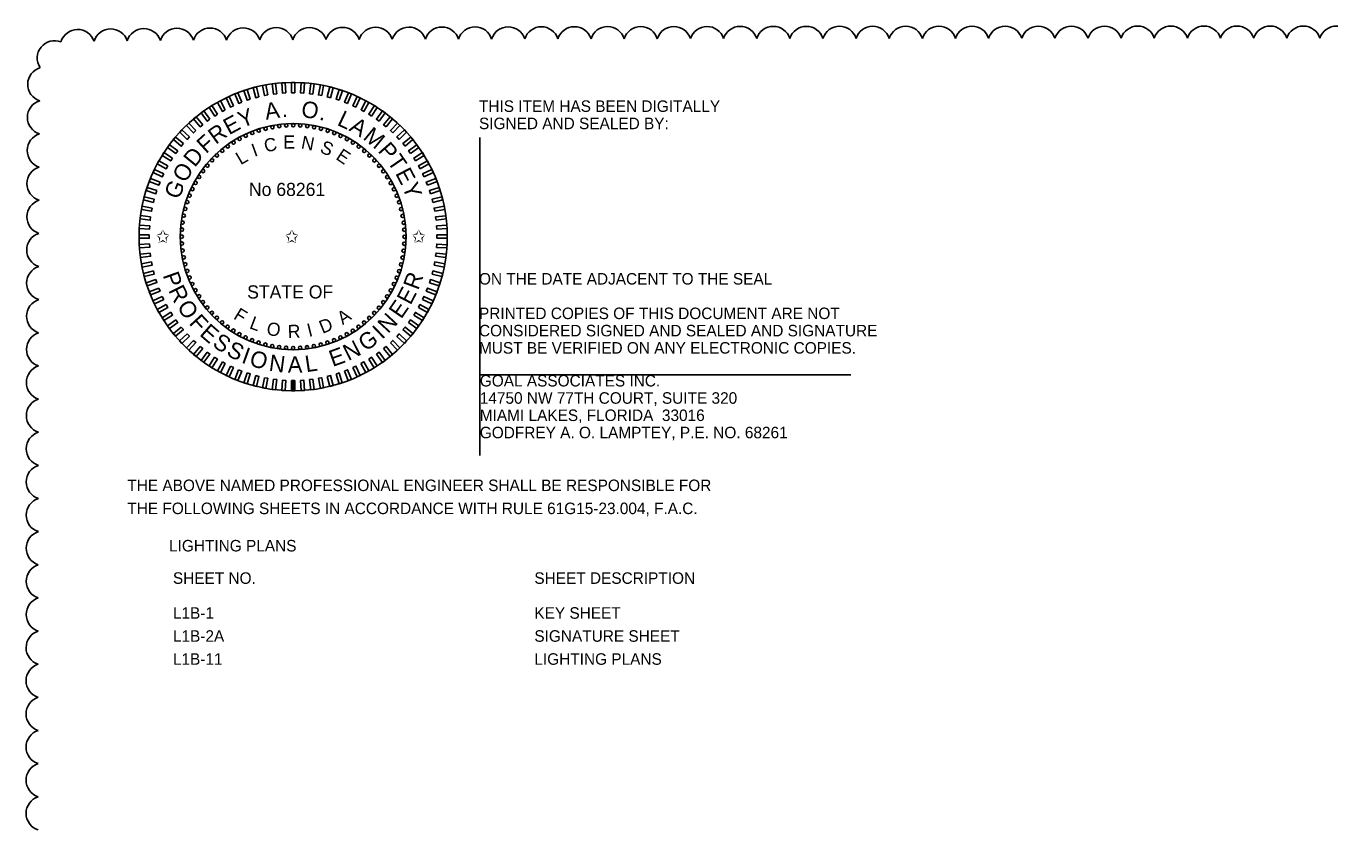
# Model space of a CAD drawing. Extents: x -811.2 to -755.6, y -2295.2 to -2235.1.
# Drawn here: x -811.11 to -803.18, y -2252.32 to -2247.44 of the extents above; entities that cross this region are included whole.
import ezdxf

# ---------------------------------------------------------------- set-up
doc = ezdxf.new("R2010")
doc.units = 0
for name, color, linetype in [('Cloud_dp', 7, 'Continuous'), ('Logo_dp', 7, 'Continuous'), ('NonPlottingEle_dp', 7, 'Continuous'), ('ScratchEle_dp', 7, 'Continuous'), ('TextMisc', 7, 'Continuous'), ('TextNotes', 7, 'Continuous')]:
    doc.layers.add(name, color=color, linetype=linetype)

msp = doc.modelspace()

# ---------------------------------------------------------------- linework, layer by layer
at = {"layer": 'Cloud_dp'}
for centre, start, end in [((-810.8012, -2247.5613), 18.59454, 163.59454), ((-810.5999, -2247.5581), 18.21421, 163.21421), ((-810.3985, -2247.5559), 18.04696, 163.04696), ((-810.197, -2247.5542), 17.94666, 162.94666), ((-809.9955, -2247.5527), 17.87787, 162.87787), ((-809.794, -2247.5515), 17.82689, 162.82689), ((-809.5924, -2247.5504), 17.78716, 162.78716), ((-809.3909, -2247.5495), 17.75505, 162.75505), ((-809.1894, -2247.5486), 17.72841, 162.72841), ((-808.9878, -2247.5478), 17.70584, 162.70584), ((-808.7863, -2247.5471), 17.6864, 162.6864), ((-808.5848, -2247.5465), 17.66942, 162.66942), ((-808.3832, -2247.546), 17.65443, 162.65443), ((-808.1817, -2247.5454), 17.64106, 162.64106), ((-807.9801, -2247.545), 17.62905, 162.62905), ((-807.7786, -2247.5445), 17.61817, 162.61817), ((-807.577, -2247.5441), 17.60826, 162.60826), ((-807.3755, -2247.5438), 17.59919, 162.59919), ((-807.174, -2247.5434), 17.59084, 162.59084), ((-806.9724, -2247.5431), 17.58312, 162.58312), ((-806.7709, -2247.5428), 17.57595, 162.57595), ((-806.5693, -2247.5426), 17.56928, 162.56928), ((-806.3678, -2247.5424), 17.56305, 162.56305), ((-806.1662, -2247.5421), 17.55721, 162.55721), ((-805.9647, -2247.5419), 17.55172, 162.55172), ((-805.7631, -2247.5418), 17.54655, 162.54655), ((-805.5616, -2247.5416), 17.54167, 162.54167), ((-805.3601, -2247.5415), 17.53705, 162.53705), ((-805.1585, -2247.5414), 17.53267, 162.53267), ((-804.957, -2247.5413), 17.52851, 162.52851), ((-804.7554, -2247.5412), 17.52455, 162.52455), ((-804.5539, -2247.5411), 17.52079, 162.52079), ((-804.3523, -2247.541), 17.51719, 162.51719), ((-804.1508, -2247.541), 17.51375, 162.51375), ((-803.9492, -2247.5409), 17.51046, 162.51046), ((-803.7477, -2247.5409), 17.50731, 162.50731), ((-803.5461, -2247.5409), 17.50428, 162.50428), ((-803.3446, -2247.5409), 17.50138, 162.50138), ((-803.143, -2247.5409), 17.5, 162.5), ((-810.9414, -2247.6297), 68.43954, 213.43954), ((-810.999, -2247.7891), 106.80445, 251.80445), ((-811.001, -2247.9905), 107.04367, 252.04367), ((-811.0025, -2248.192), 107.15618, 252.15618), ((-811.0035, -2248.3935), 107.22533, 252.22533), ((-811.0044, -2248.595), 107.27338, 252.27338), ((-811.0052, -2248.7966), 107.30928, 252.30928), ((-811.0058, -2248.9981), 107.33743, 252.33743), ((-811.0063, -2249.1996), 107.36027, 252.36027), ((-811.0068, -2249.4012), 107.37928, 252.37928), ((-811.0072, -2249.6027), 107.39543, 252.39543), ((-811.0075, -2249.8042), 107.40937, 252.40937), ((-811.0078, -2250.0058), 107.42156, 252.42156), ((-811.0081, -2250.2073), 107.43234, 252.43234), ((-811.0083, -2250.4089), 107.44197, 252.44197), ((-811.0085, -2250.6104), 107.45063, 252.45063), ((-811.0086, -2250.812), 107.45847, 252.45847), ((-811.0088, -2251.0135), 107.46563, 252.46563), ((-811.0089, -2251.2151), 107.47218, 252.47218), ((-811.009, -2251.4166), 107.47822, 252.47822), ((-811.009, -2251.6181), 107.4838, 252.4838), ((-811.0091, -2251.8197), 107.48899, 252.48899), ((-811.0091, -2252.0212), 107.49382, 252.49382), ((-811.0091, -2252.2228), 107.49843, 252.49843)]:
    msp.add_arc(centre, 0.1057, start, end, dxfattribs=at)
at = {"layer": 'Logo_dp'}
for p, q in [((-809.5001, -2249.6532), (-809.5003, -2249.5907)), ((-809.4901, -2249.6531), (-809.4903, -2249.5906)), ((-809.4801, -2249.6531), (-809.4803, -2249.5906))]:
    msp.add_line(p, q, dxfattribs=at)
for points in [[(-809.5897, -2247.8462), (-809.6097, -2247.8488), (-809.6175, -2247.7868), (-809.5975, -2247.7843)], [(-809.5349, -2247.8417), (-809.555, -2247.843), (-809.559, -2247.7806), (-809.5388, -2247.7794)], [(-809.4799, -2247.8406), (-809.5001, -2247.8406), (-809.5001, -2247.7782), (-809.4799, -2247.7782)], [(-809.425, -2247.843), (-809.4452, -2247.8417), (-809.4412, -2247.7794), (-809.4211, -2247.7807)], [(-809.3703, -2247.8488), (-809.3904, -2247.8463), (-809.3825, -2247.7843), (-809.3625, -2247.7868)], [(-809.8535, -2247.9195), (-809.8717, -2247.9281), (-809.8983, -2247.8716), (-809.8801, -2247.863)], [(-809.8028, -2247.8983), (-809.8215, -2247.9057), (-809.8445, -2247.8477), (-809.8258, -2247.8402)], [(-809.7508, -2247.8803), (-809.77, -2247.8865), (-809.7893, -2247.8271), (-809.7701, -2247.8209)], [(-809.6979, -2247.8656), (-809.7174, -2247.8706), (-809.7329, -2247.8101), (-809.7134, -2247.8051)], [(-809.6441, -2247.8542), (-809.6639, -2247.858), (-809.6756, -2247.7966), (-809.6558, -2247.7929)], [(-809.3162, -2247.858), (-809.336, -2247.8542), (-809.3243, -2247.7929), (-809.3045, -2247.7967)], [(-809.2626, -2247.8706), (-809.2822, -2247.8656), (-809.2667, -2247.8051), (-809.2471, -2247.8102)], [(-809.21, -2247.8866), (-809.2292, -2247.8803), (-809.2099, -2247.821), (-809.1907, -2247.8272)], [(-809.1585, -2247.9058), (-809.1773, -2247.8984), (-809.1543, -2247.8403), (-809.1355, -2247.8477)], [(-809.1083, -2247.9282), (-809.1266, -2247.9196), (-809.1, -2247.8631), (-809.0817, -2247.8717)], [(-809.9504, -2247.9714), (-809.9674, -2247.9822), (-810.0009, -2247.9295), (-809.9838, -2247.9186)], [(-809.9027, -2247.9439), (-809.9204, -2247.9537), (-809.9505, -2247.8989), (-809.9328, -2247.8892)], [(-809.0596, -2247.9537), (-809.0773, -2247.944), (-809.0473, -2247.8893), (-809.0296, -2247.899)], [(-809.0127, -2247.9823), (-809.0297, -2247.9715), (-808.9962, -2247.9187), (-808.9792, -2247.9296)], [(-810.0817, -2248.0708), (-810.0964, -2248.0846), (-810.1392, -2248.0391), (-810.1244, -2248.0253)], [(-810.04, -2248.0349), (-810.0556, -2248.0478), (-810.0954, -2247.9997), (-810.0798, -2247.9868)], [(-809.9962, -2248.0017), (-810.0125, -2248.0136), (-810.0492, -2247.9631), (-810.0329, -2247.9512)], [(-808.9676, -2248.0137), (-808.9839, -2248.0018), (-808.9472, -2247.9513), (-808.9308, -2247.9632)], [(-808.9245, -2248.0479), (-808.9401, -2248.035), (-808.9003, -2247.9869), (-808.8847, -2247.9998)], [(-808.8837, -2248.0847), (-808.8984, -2248.0709), (-808.8557, -2248.0254), (-808.841, -2248.0392)], [(-810.121, -2248.1092), (-810.1348, -2248.1239), (-810.1804, -2248.0812), (-810.1665, -2248.0665)], [(-808.8453, -2248.1241), (-808.8591, -2248.1093), (-808.8136, -2248.0666), (-808.7998, -2248.0813)], [(-810.192, -2248.1931), (-810.2039, -2248.2094), (-810.2544, -2248.1727), (-810.2426, -2248.1564)], [(-810.1579, -2248.15), (-810.1707, -2248.1656), (-810.2188, -2248.1258), (-810.206, -2248.1102)], [(-808.8094, -2248.1657), (-808.8223, -2248.1502), (-808.7742, -2248.1104), (-808.7613, -2248.1259)], [(-808.7762, -2248.2095), (-808.7881, -2248.1932), (-808.7376, -2248.1565), (-808.7257, -2248.1728)], [(-810.252, -2248.2852), (-810.2617, -2248.3028), (-810.3164, -2248.2728), (-810.3067, -2248.2551)], [(-810.2235, -2248.2382), (-810.2343, -2248.2552), (-810.287, -2248.2218), (-810.2762, -2248.2047)], [(-808.7459, -2248.2554), (-808.7567, -2248.2383), (-808.7039, -2248.2049), (-808.6931, -2248.2219)], [(-808.7184, -2248.303), (-808.7281, -2248.2853), (-808.6734, -2248.2552), (-808.6637, -2248.2729)], [(-810.2775, -2248.3338), (-810.2861, -2248.3521), (-810.3426, -2248.3255), (-810.334, -2248.3073)], [(-808.694, -2248.3523), (-808.7026, -2248.334), (-808.6461, -2248.3074), (-808.6375, -2248.3257)], [(-810.3192, -2248.4355), (-810.3254, -2248.4547), (-810.3848, -2248.4355), (-810.3786, -2248.4163)], [(-810.3, -2248.384), (-810.3074, -2248.4028), (-810.3654, -2248.3798), (-810.358, -2248.3611)], [(-808.6728, -2248.403), (-808.6802, -2248.3842), (-808.6222, -2248.3612), (-808.6147, -2248.38)], [(-808.6548, -2248.4549), (-808.661, -2248.4357), (-808.6016, -2248.4164), (-808.5954, -2248.4356)], [(-810.3351, -2248.4882), (-810.3401, -2248.5077), (-810.4006, -2248.4922), (-810.3956, -2248.4726)], [(-808.64, -2248.5079), (-808.6451, -2248.4883), (-808.5846, -2248.4728), (-808.5796, -2248.4924)], [(-810.3477, -2248.5417), (-810.3515, -2248.5615), (-810.4129, -2248.5498), (-810.4091, -2248.53)], [(-808.6287, -2248.5617), (-808.6325, -2248.5418), (-808.5711, -2248.5301), (-808.5673, -2248.55)], [(-810.3628, -2248.6505), (-810.3641, -2248.6707), (-810.4264, -2248.6668), (-810.4251, -2248.6466)], [(-810.357, -2248.5959), (-810.3595, -2248.6159), (-810.4215, -2248.6081), (-810.4189, -2248.588)], [(-808.6207, -2248.6161), (-808.6232, -2248.596), (-808.5613, -2248.5882), (-808.5588, -2248.6082)], [(-808.6162, -2248.6709), (-808.6174, -2248.6507), (-808.5551, -2248.6468), (-808.5539, -2248.6669)], [(-810.3652, -2248.7054), (-810.3652, -2248.7256), (-810.4276, -2248.7256), (-810.4276, -2248.7054)], [(-808.6151, -2248.7258), (-808.6151, -2248.7056), (-808.5527, -2248.7056), (-808.5527, -2248.7258)], [(-810.3641, -2248.7604), (-810.3628, -2248.7806), (-810.4251, -2248.7845), (-810.4264, -2248.7643)], [(-810.3595, -2248.8152), (-810.357, -2248.8352), (-810.4189, -2248.8431), (-810.4215, -2248.823)], [(-808.6233, -2248.8354), (-808.6207, -2248.8154), (-808.5588, -2248.8232), (-808.5613, -2248.8432)], [(-808.6175, -2248.7807), (-808.6162, -2248.7606), (-808.5539, -2248.7645), (-808.5551, -2248.7847)], [(-810.3516, -2248.8696), (-810.3478, -2248.8894), (-810.4091, -2248.9011), (-810.4129, -2248.8813)], [(-808.6325, -2248.8896), (-808.6287, -2248.8698), (-808.5674, -2248.8815), (-808.5712, -2248.9013)], [(-810.3402, -2248.9234), (-810.3352, -2248.9429), (-810.3957, -2248.9585), (-810.4007, -2248.9389)], [(-810.3255, -2248.9763), (-810.3192, -2248.9955), (-810.3786, -2249.0148), (-810.3849, -2248.9956)], [(-808.6611, -2248.9957), (-808.6548, -2248.9765), (-808.5954, -2248.9958), (-808.6017, -2249.015)], [(-808.6451, -2248.9431), (-808.6401, -2248.9236), (-808.5796, -2248.9391), (-808.5846, -2248.9586)], [(-810.3075, -2249.0283), (-810.3, -2249.0471), (-810.3581, -2249.07), (-810.3655, -2249.0513)], [(-808.6803, -2249.0472), (-808.6729, -2249.0285), (-808.6148, -2249.0514), (-808.6222, -2249.0702)], [(-810.2862, -2249.079), (-810.2776, -2249.0973), (-810.3341, -2249.1238), (-810.3427, -2249.1056)], [(-810.2618, -2249.1283), (-810.2521, -2249.1459), (-810.3068, -2249.176), (-810.3165, -2249.1583)], [(-808.7282, -2249.1461), (-808.7185, -2249.1284), (-808.6638, -2249.1585), (-808.6735, -2249.1762)], [(-808.7027, -2249.0974), (-808.6941, -2249.0792), (-808.6376, -2249.1057), (-808.6462, -2249.124)], [(-810.2344, -2249.1759), (-810.2236, -2249.1929), (-810.2763, -2249.2264), (-810.2871, -2249.2094)], [(-808.7568, -2249.1931), (-808.746, -2249.1761), (-808.6932, -2249.2095), (-808.704, -2249.2266)], [(-810.204, -2249.2217), (-810.1922, -2249.2381), (-810.2427, -2249.2748), (-810.2545, -2249.2584)], [(-810.1708, -2249.2656), (-810.158, -2249.2811), (-810.2061, -2249.3209), (-810.2189, -2249.3054)], [(-808.8224, -2249.2812), (-808.8095, -2249.2657), (-808.7614, -2249.3055), (-808.7743, -2249.321)], [(-808.7882, -2249.2382), (-808.7763, -2249.2219), (-808.7258, -2249.2586), (-808.7377, -2249.2749)], [(-810.135, -2249.3072), (-810.1211, -2249.3219), (-810.1667, -2249.3647), (-810.1805, -2249.35)], [(-810.0965, -2249.3465), (-810.0818, -2249.3603), (-810.1246, -2249.4059), (-810.1393, -2249.392)], [(-808.8985, -2249.3605), (-808.8838, -2249.3467), (-808.8411, -2249.3922), (-808.8558, -2249.406)], [(-808.8592, -2249.3221), (-808.8454, -2249.3073), (-808.7999, -2249.3501), (-808.8137, -2249.3648)], [(-810.0557, -2249.3834), (-810.0402, -2249.3962), (-810.08, -2249.4443), (-810.0955, -2249.4315)], [(-810.0127, -2249.4176), (-809.9964, -2249.4294), (-810.0331, -2249.4799), (-810.0494, -2249.4681)], [(-809.9676, -2249.449), (-809.9505, -2249.4598), (-809.984, -2249.5125), (-810.001, -2249.5017)], [(-809.0299, -2249.4599), (-809.0128, -2249.4491), (-808.9794, -2249.5018), (-808.9964, -2249.5126)], [(-808.984, -2249.4295), (-808.9677, -2249.4177), (-808.931, -2249.4682), (-808.9473, -2249.4801)], [(-808.9402, -2249.3964), (-808.9247, -2249.3835), (-808.8848, -2249.4316), (-808.9004, -2249.4445)], [(-809.9206, -2249.4775), (-809.9029, -2249.4872), (-809.933, -2249.542), (-809.9507, -2249.5322)], [(-809.8719, -2249.503), (-809.8536, -2249.5116), (-809.8802, -2249.5681), (-809.8985, -2249.5595)], [(-809.8217, -2249.5255), (-809.8029, -2249.5329), (-809.8259, -2249.591), (-809.8447, -2249.5835)], [(-809.1775, -2249.533), (-809.1587, -2249.5255), (-809.1357, -2249.5836), (-809.1545, -2249.591)], [(-809.1268, -2249.5117), (-809.1085, -2249.5031), (-809.0819, -2249.5596), (-809.1002, -2249.5682)], [(-809.0775, -2249.4873), (-809.0598, -2249.4776), (-809.0297, -2249.5323), (-809.0474, -2249.5421)], [(-809.7702, -2249.5447), (-809.751, -2249.5509), (-809.7703, -2249.6103), (-809.7895, -2249.6041)], [(-809.7176, -2249.5606), (-809.698, -2249.5657), (-809.7136, -2249.6261), (-809.7331, -2249.6211)], [(-809.6641, -2249.5733), (-809.6443, -2249.577), (-809.656, -2249.6384), (-809.6758, -2249.6346)], [(-809.6099, -2249.5825), (-809.5899, -2249.585), (-809.5977, -2249.647), (-809.6177, -2249.6444)], [(-809.5552, -2249.5883), (-809.5351, -2249.5896), (-809.539, -2249.6519), (-809.5592, -2249.6506)], [(-809.5003, -2249.5907), (-809.4801, -2249.5907), (-809.4801, -2249.6531), (-809.5003, -2249.6531)], [(-809.4453, -2249.5896), (-809.4252, -2249.5883), (-809.4213, -2249.6506), (-809.4414, -2249.6519)], [(-809.3906, -2249.585), (-809.3705, -2249.5825), (-809.3627, -2249.6445), (-809.3827, -2249.647)], [(-809.3362, -2249.5771), (-809.3163, -2249.5733), (-809.3046, -2249.6346), (-809.3245, -2249.6384)], [(-809.2824, -2249.5657), (-809.2628, -2249.5607), (-809.2473, -2249.6212), (-809.2668, -2249.6262)], [(-809.2294, -2249.551), (-809.2102, -2249.5447), (-809.1909, -2249.6041), (-809.2101, -2249.6104)]]:
    msp.add_lwpolyline(points, close=True, dxfattribs=at)
for centre in [(-809.7781, -2248.1024), (-809.739, -2248.0855), (-809.6989, -2248.0712), (-809.6581, -2248.0593), (-809.6165, -2248.0501), (-809.5745, -2248.0434), (-809.5321, -2248.0395), (-809.4896, -2248.0382), (-809.447, -2248.0395), (-809.4047, -2248.0436), (-809.3626, -2248.0503), (-809.3211, -2248.0596), (-809.2802, -2248.0715), (-809.2402, -2248.0859), (-809.2012, -2248.1029), (-809.9215, -2248.1933), (-809.8879, -2248.1672), (-809.8527, -2248.1433), (-809.816, -2248.1217), (-809.1633, -2248.1222), (-809.1266, -2248.1439), (-809.0915, -2248.1679), (-809.0579, -2248.194), (-809.9836, -2248.2515), (-809.9535, -2248.2214), (-809.026, -2248.2222), (-808.9959, -2248.2523), (-810.0618, -2248.3522), (-810.0379, -2248.317), (-810.0118, -2248.2834), (-808.9678, -2248.2842), (-808.9417, -2248.3179), (-808.9178, -2248.3531), (-810.1029, -2248.4267), (-810.0835, -2248.3888), (-808.8962, -2248.3898), (-808.8769, -2248.4277), (-810.1343, -2248.5057), (-810.1198, -2248.4657), (-808.86, -2248.4668), (-808.8456, -2248.5068), (-810.1555, -2248.5881), (-810.1462, -2248.5466), (-808.8338, -2248.5477), (-808.8245, -2248.5892), (-810.1622, -2248.6302), (-808.8179, -2248.6313), (-810.1676, -2248.7151), (-810.1662, -2248.6725), (-808.814, -2248.6737), (-808.8127, -2248.7162), (-810.1663, -2248.7576), (-810.1623, -2248.8), (-808.8181, -2248.8011), (-808.814, -2248.7587), (-810.1557, -2248.842), (-810.1464, -2248.8836), (-808.8341, -2248.8847), (-808.8248, -2248.8431), (-810.1346, -2248.9244), (-810.1202, -2248.9645), (-808.8604, -2248.9656), (-808.846, -2248.9255), (-810.1034, -2249.0036), (-810.0841, -2249.0415), (-808.8967, -2249.0425), (-808.8774, -2249.0046), (-810.0624, -2249.0782), (-810.0385, -2249.1134), (-808.9424, -2249.1143), (-808.9184, -2249.0791), (-810.0125, -2249.147), (-809.9844, -2249.179), (-809.9543, -2249.2091), (-809.0268, -2249.2099), (-808.9967, -2249.1798), (-808.9685, -2249.1479), (-809.9224, -2249.2373), (-809.8888, -2249.2634), (-809.8536, -2249.2873), (-809.1276, -2249.2879), (-809.0924, -2249.264), (-809.0587, -2249.238), (-809.817, -2249.309), (-809.7791, -2249.3284), (-809.74, -2249.3453), (-809.7, -2249.3598), (-809.6591, -2249.3717), (-809.6176, -2249.381), (-809.3637, -2249.3812), (-809.3222, -2249.372), (-809.2813, -2249.3601), (-809.2413, -2249.3457), (-809.2022, -2249.3289), (-809.1642, -2249.3096), (-809.5756, -2249.3877), (-809.5332, -2249.3917), (-809.4901, -2249.3931), (-809.4481, -2249.3918), (-809.4058, -2249.3878)]:
    msp.add_circle(centre, 0.01, dxfattribs=at)
at = {"layer": 'NonPlottingEle_dp'}
for radius in [0.9375, 0.6875]:
    msp.add_circle((-809.4901, -2248.7156), radius, dxfattribs=at)
at = {"layer": 'ScratchEle_dp'}
for p, q in [((-808.3546, -2248.1122), (-808.3546, -2250.0469)), ((-808.3546, -2249.5569), (-806.0979, -2249.5569))]:
    msp.add_line(p, q, dxfattribs=at)

# ---------------------------------------------------------------- texts
at = {"layer": 'Logo_dp'}
for s, height, rotation, p in [('Y', 0.1, 21.06329, (-809.8021, -2248.0562)), ('A', 0.1, 8.80884, (-809.6551, -2248.005)), ('O', 0.1, 352.18771, (-809.4449, -2247.9875)), ('E', 0.1, 28.10553, (-809.8806, -2248.0994)), ('.', 0.1, 1.04184, (-809.5575, -2247.9892)), ('.', 0.1, 343.52684, (-809.3358, -2248.0026)), ('L', 0.1, 334.67271, (-809.2279, -2248.0349)), ('A', 0.1, 328.40959, (-809.1552, -2248.0676)), ('F', 0.1, 42.37723, (-810.0205, -2248.2147)), ('R', 0.1, 35.92688, (-809.9609, -2248.1583)), ('E', 0.08, 0.41861, (-809.5498, -2248.1806)), ('N', 0.08, 349.29143, (-809.4455, -2248.1791)), ('M', 0.1, 320.6426, (-809.0707, -2248.1188)), ('D', 0.1, 50.8569, (-810.0886, -2248.2984)), ('I', 0.08, 20.01168, (-809.7258, -2248.2316)), ('C', 0.08, 12.20255, (-809.6579, -2248.204)), ('S', 0.08, 337.02207, (-809.3325, -2248.2008)), ('E', 0.08, 325.86633, (-809.2358, -2248.2411)), ('P', 0.1, 311.19658, (-808.9784, -2248.1957)), ('L', 0.08, 30.40215, (-809.8093, -2248.282)), ('T', 0.1, 304.45632, (-808.9209, -2248.2594)), ('O', 0.1, 59.51777, (-810.1446, -2248.3933)), ('E', 0.1, 297.63152, (-808.8707, -2248.3302)), ('G', 0.1, 68.0518, (-810.1851, -2248.494)), ('Y', 0.1, 290.58928, (-808.8281, -2248.4091)), ('P', 0.1, 289.40551, (-810.2848, -2248.9502)), ('R', 0.1, 69.5134, (-808.7299, -2249.0453)), ('R', 0.1, 296.14576, (-810.2518, -2249.0419)), ('E', 0.1, 62.47116, (-808.7761, -2249.136)), ('O', 0.1, 303.96711, (-810.2003, -2249.1425)), ('E', 0.1, 55.42892, (-808.833, -2249.2204)), ('F', 0.1, 312.62798, (-810.1279, -2249.2446)), ('F', 0.08, 328.72408, (-809.8582, -2249.2122)), ('L', 0.08, 339.29159, (-809.7609, -2249.2713)), ('D', 0.08, 22.01279, (-809.312, -2249.3075)), ('A', 0.08, 34.49917, (-809.1883, -2249.255)), ('N', 0.1, 47.17876, (-808.9123, -2249.3095)), ('E', 0.1, 319.07833, (-810.0645, -2249.3129)), ('O', 0.08, 349.68206, (-809.6562, -2249.311)), ('R', 0.08, 2.33977, (-809.5217, -2249.3329)), ('I', 0.08, 14.20366, (-809.3941, -2249.3262)), ('G', 0.1, 35.11153, (-809.0492, -2249.4172)), ('I', 0.1, 43.64556, (-808.9499, -2249.344)), ('S', 0.1, 326.12056, (-809.9869, -2249.3788)), ('S', 0.1, 333.193, (-809.9015, -2249.4349)), ('N', 0.1, 26.86136, (-809.1544, -2249.4732)), ('I', 0.1, 340.26543, (-809.8098, -2249.4801)), ('O', 0.1, 343.79863, (-809.7621, -2249.4983)), ('N', 0.1, 352.45949, (-809.6411, -2249.5304)), ('A', 0.1, 0.70966, (-809.5227, -2249.5436)), ('L', 0.1, 8.47665, (-809.4105, -2249.5404)), ('E', 0.1, 19.81912, (-809.2498, -2249.5086))]:
    msp.add_text(s, height=height, rotation=rotation, dxfattribs=at).set_placement(p)
for s, p in [('No 68261', (-809.7591, -2248.4684)), ('✩', (-810.3251, -2248.7536)), ('✩', (-809.5404, -2248.7536)), ('✩', (-808.7685, -2248.7536)), ('STATE OF', (-809.7698, -2249.0918))]:
    msp.add_text(s, height=0.08, dxfattribs=at).set_placement(p)
at = {"layer": 'TextMisc'}
for s, p in [('THIS ITEM HAS BEEN DIGITALLY', (-808.3596, -2247.9571)), ('SIGNED AND SEALED BY:', (-808.3596, -2248.0621)), ('ON THE DATE ADJACENT TO THE SEAL', (-808.3596, -2249.0071)), ('PRINTED COPIES OF THIS DOCUMENT ARE NOT ', (-808.3596, -2249.2171)), ('CONSIDERED SIGNED AND SEALED AND SIGNATURE ', (-808.3596, -2249.3221)), ('MUST BE VERIFIED ON ANY ELECTRONIC COPIES.', (-808.3596, -2249.4271)), ('GOAL ASSOCIATES INC.', (-808.3546, -2249.6269)), ('14750 NW 77TH COURT, SUITE 320', (-808.3546, -2249.7319)), ('MIAMI LAKES, FLORIDA  33016', (-808.3546, -2249.8369)), ('GODFREY A. O. LAMPTEY, P.E. NO. 68261', (-808.3546, -2249.9419)), ('THE ABOVE NAMED PROFESSIONAL ENGINEER SHALL BE RESPONSIBLE FOR ', (-810.4987, -2250.2631)), ('THE FOLLOWING SHEETS IN ACCORDANCE WITH RULE 61G15-23.004, F.A.C.', (-810.4987, -2250.4031)), ('LIGHTING PLANS', (-810.245, -2250.6301))]:
    msp.add_text(s, height=0.07, dxfattribs=at).set_placement(p)
at = {"layer": 'TextNotes'}
for s, p in [('SHEET NO.', (-810.2215, -2250.8271)), ('SHEET DESCRIPTION', (-808.0226, -2250.8271)), ('L1B-1', (-810.2215, -2251.0393)), ('KEY SHEET', (-808.0226, -2251.0393)), ('L1B-2A', (-810.2215, -2251.1793)), ('SIGNATURE SHEET', (-808.0226, -2251.1793)), ('L1B-11', (-810.2215, -2251.3193)), ('LIGHTING PLANS', (-808.0226, -2251.3193))]:
    msp.add_text(s, height=0.07, dxfattribs=at).set_placement(p)

doc.saveas('drawing.dxf')
